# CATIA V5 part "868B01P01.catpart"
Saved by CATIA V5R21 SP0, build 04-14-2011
Part number: 868B01P01
Bounding box of the stored display mesh (mm): x -2.25 to 2.25, y -50.75 to 50.75, z -39.5 to 25.5
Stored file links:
  C:\Users\ALI OZGUN\Desktop\alhan\868B01P01.CATPart
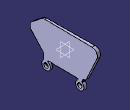
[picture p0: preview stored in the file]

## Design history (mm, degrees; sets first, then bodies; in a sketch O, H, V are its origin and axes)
Body1 (main body)
  Sketch1 on yz-plane, origin (0, 0, 0), H (0, 1, 0), V (0, 0, 1)
    point P1 (-23.75, -25.5)
    line L1 (-23.5056, -25.5) -> (20.8133, -25.5)
    point P2 (30.75, -25.5)
    line L2 (34.0752, -20.0327) -> (50.0005, 14.1191)
    line L3 (42.75, 25.5) -> (-28.7278, 25.5)
    line L4 (-33.6655, 23.7943) -> (-47.6877, 12.7943)
    line L5 (-48.59, 1.0325) -> (-31.9471, -16.7444)
    arc A1 centre (-42.75, 6.5) radius 8 from (-47.6877, 12.7943) to (-48.59, 1.0325) ccw
    point P5 (-42.75, 6.5)
    arc A2 centre (-28.7278, 17.5) radius 8 from (-33.6655, 23.7943) to (-28.7278, 25.5) cw
    arc A3 centre (42.75, 17.5) radius 8 from (42.75, 25.5) to (50.0005, 14.1191) cw
    arc A4 centre (-26.748, -33.1) radius 6.4 from (-31.5845, -28.9086) to (-23.7635, -27.4385) ccw
    point P12 (-26.748, -33.1)
    arc A5 centre (24.052, -33.1) radius 6.4 from (20.9981, -27.4756) to (27.8597, -27.956) ccw
    point P13 (24.052, -33.1)
    axis line L6 (24.052, -33.1) -> (-26.748, -33.1)
    circle A6 centre (24.052, -33.1) radius 3.25
    circle A7 centre (-26.748, -33.1) radius 3.25
    line L7 (-30.248, -25.3256) -> (-30.248, -21.0454)
    line L8 (-24.248, -26.6354) -> (-24.248, -26.2424)
    line L9 (27.552, -27.3453) -> (27.552, -26.3422)
    line L10 (21.552, -26.5445) -> (21.552, -26.2387)
    point P14 (-30.248, -18.5593)
    line L11 (31.552, -22.3422) -> (30.45, -22.3422)
    arc A8 centre (30.45, -18.3422) radius 4 from (34.0752, -20.0327) to (30.45, -22.3422) cw
    arc A9 centre (31.552, -26.3422) radius 4 from (31.552, -22.3422) to (27.552, -26.3422) ccw
    arc A10 centre (28.3118, -27.3453) radius 0.7598 from (27.8597, -27.956) to (27.552, -27.3453) cw
    arc A11 centre (20.4925, -26.5445) radius 1.0595 from (20.9981, -27.4756) to (21.552, -26.5445) ccw
    arc A12 centre (20.8133, -26.2387) radius 0.7387 from (20.8133, -25.5) to (21.552, -26.2387) cw
    arc A13 centre (-23.3402, -26.6354) radius 0.9078 from (-23.7635, -27.4385) to (-24.248, -26.6354) cw
    arc A14 centre (-23.5056, -26.2424) radius 0.7424 from (-24.248, -26.2424) to (-23.5056, -25.5) cw
    arc A15 centre (-36.5411, -21.0454) radius 6.2931 from (-30.248, -21.0454) to (-31.9471, -16.7444) ccw
    arc A16 centre (-35.7189, -25.3256) radius 5.4709 from (-31.5845, -28.9086) to (-30.248, -25.3256) ccw
    distance L3 L1 = 51
    radius A1 = 8
    radius A2 = 8
    radius A3 = 8
    distance A1 A3 H = 101.5
    distance P5 L1 = 32
    distance P1 A1 H = 27
    distance P2 A3 H = 20
    angle L4 L5 = 85
    distance H L1 = 25.5
    distance V A3 = 50.75
    distance P12 P13 H = 50.8
    distance A5 L3 = 65
    radius A4 = 6.4
    radius A5 = 6.4
    radius A6 = 3.25
    radius A7 = 3.25
    distance L10 L9 = 6
    distance L8 L7 = 6
    distance L7 P12 = 3.5
    distance L9 P13 = 3.5
    angle L2 L1 = 115
    radius A8 = 4
    radius A9 = 4 {= Sketch1.radius(A8)}
    radius A10 = 0.7598
    radius A11 = 1.0595
    radius A12 = 0.7387
    radius A13 = 0.9078
    radius A14 = 0.7424
    radius A15 = 6.2931
    radius A16 = 5.4709
    horizontal: L1 H, L3 H, L6 H, L11 H
    tangency: A1 L4, A1 L5, A2 L4, A2 L3, A3 L3, A3 L2, A8 L2, A8 L11, A9 L11, A9 L9, A10 L9, A10 A5, A11 A5, A11 L10, A12 L1, A12 L10, A13 A4, A13 L8, A14 L8, A14 L1, A15 L7, A15 L5, A16 A4, A16 L7
    vertical: L7 V, L8 V, L9 V, L10 V
    coincidence: L7 P14, P1 L1, L5 P14
  Pad1: profile Sketch1, direction (1, 0, 0), length 2.25, mirrored extent
  Sketch2 on xy-plane, origin (0, 0, 0), H (1, 0, 0), V (0, 1, 0)
    line L1 (-2.4036, 66.3413) -> (-1.2079, -55.0156)
    point P1 (-2.4036, 66.3413)
    point P2 (-1.2079, -55.0156)
    point P3 (-2.25, 50.75)
    point P6 (-2.25, -50.75)
    point P7 (1.2079, -55.0156)
    point P8 (2.4036, 66.3413)
    line L2 (2.4036, 66.3413) -> (1.2079, -55.0156)
    line L3 (-2.4036, 66.3413) -> (2.4036, 66.3413)
    distance L1 P6 = 1
    coincidence: L1 P3
    symmetry: P2 P7 V, P1 P8 V, L1 L2 V
    horizontal: L3 H
  Pocket1: profile Sketch2, direction (0, 0, -1), length 43.25, mirrored extent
